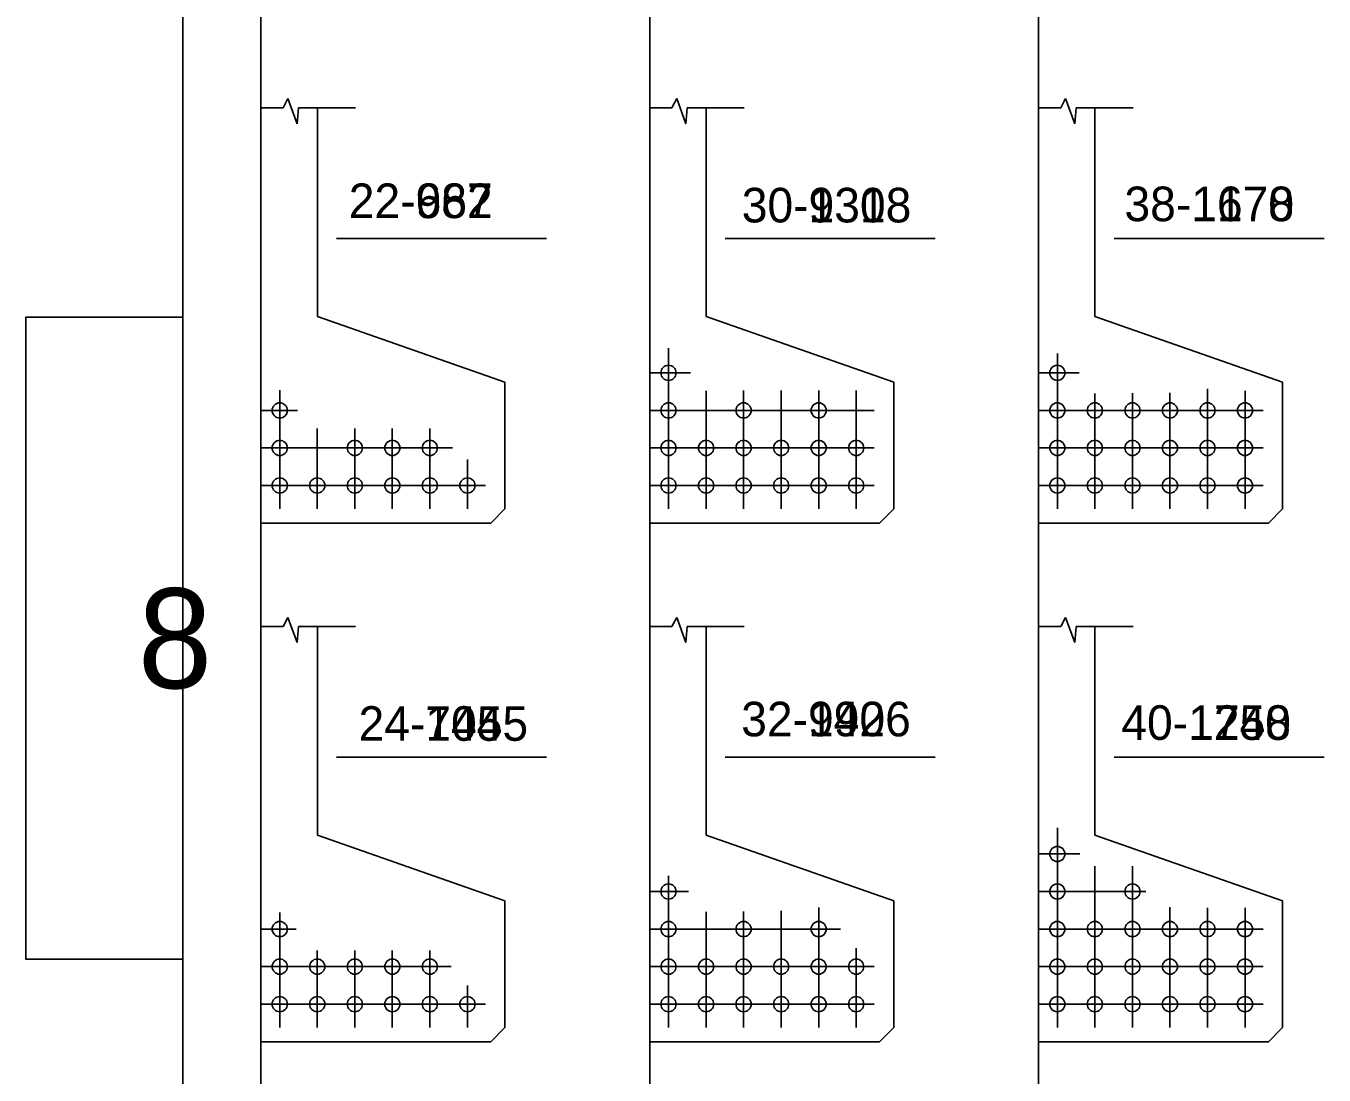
# Model space of a CAD drawing. Extents: x 1005.2 to 1101.8, y 1997.9 to 2073.7.
# Drawn here: x 1012.25 to 1024.77, y 2019.94 to 2030.05 of the extents above; entities that cross this region are included whole.
import ezdxf

# ---------------------------------------------------------------- set-up
doc = ezdxf.new("R2010")
doc.units = 0
for name, color, linetype in [('Level 1', 7, 'Continuous'), ('Level 8', 7, 'Continuous'), ('Level 9', 7, 'Continuous')]:
    doc.layers.add(name, color=color, linetype=linetype)

msp = doc.modelspace()

# ---------------------------------------------------------------- linework, layer by layer
at = {"layer": 'Level 1'}
msp.add_line((1013.763, 2012.562), (1013.763, 2068.561), dxfattribs=at)
msp.add_lwpolyline([(1013.763, 2027.241), (1012.249, 2027.241), (1012.249, 2021.051), (1013.763, 2021.051)], close=True, dxfattribs=at)
at = {"layer": 'Level 8'}
for p, q in [((1014.516, 2014.747), (1014.516, 2034.639)), ((1018.266, 2014.747), (1018.266, 2034.639)), ((1022.016, 2014.747), (1022.016, 2034.639)), ((1014.729, 2029.258), (1014.776, 2029.347)), ((1014.776, 2029.347), (1014.865, 2029.104)), ((1018.479, 2029.258), (1018.526, 2029.347)), ((1018.526, 2029.347), (1018.615, 2029.104)), ((1022.229, 2029.258), (1022.276, 2029.347)), ((1022.276, 2029.347), (1022.365, 2029.104)), ((1014.516, 2029.258), (1014.729, 2029.258)), ((1014.865, 2029.104), (1014.878, 2029.258)), ((1014.878, 2029.258), (1015.427, 2029.258)), ((1015.06, 2027.248), (1015.06, 2029.258)), ((1018.266, 2029.258), (1018.479, 2029.258)), ((1018.615, 2029.104), (1018.628, 2029.258)), ((1018.628, 2029.258), (1019.177, 2029.258)), ((1018.81, 2027.248), (1018.81, 2029.258)), ((1022.016, 2029.258), (1022.229, 2029.258)), ((1022.365, 2029.104), (1022.378, 2029.258)), ((1022.378, 2029.258), (1022.927, 2029.258)), ((1022.56, 2027.248), (1022.56, 2029.258)), ((1015.244, 2027.998), (1017.269, 2027.998)), ((1018.994, 2027.998), (1021.019, 2027.998)), ((1022.744, 2027.998), (1024.769, 2027.998)), ((1015.06, 2027.248), (1016.869, 2026.614)), ((1018.81, 2027.248), (1020.619, 2026.614)), ((1022.56, 2027.248), (1024.369, 2026.614)), ((1018.447, 2025.392), (1018.447, 2026.941)), ((1022.197, 2025.392), (1022.197, 2026.89)), ((1018.659, 2026.704), (1018.266, 2026.704)), ((1022.408, 2026.704), (1022.016, 2026.704)), ((1016.869, 2025.392), (1016.869, 2026.614)), ((1020.619, 2025.392), (1020.619, 2026.614)), ((1024.369, 2025.392), (1024.369, 2026.614)), ((1014.697, 2025.392), (1014.697, 2026.536)), ((1018.809, 2025.392), (1018.809, 2026.53)), ((1019.171, 2025.392), (1019.171, 2026.534)), ((1019.533, 2025.392), (1019.533, 2026.534)), ((1019.895, 2025.392), (1019.895, 2026.534)), ((1020.257, 2025.392), (1020.257, 2026.534)), ((1022.559, 2025.392), (1022.559, 2026.504)), ((1022.921, 2025.392), (1022.921, 2026.508)), ((1023.283, 2025.392), (1023.283, 2026.512)), ((1023.645, 2025.392), (1023.645, 2026.55)), ((1024.007, 2025.392), (1024.007, 2026.529)), ((1014.87, 2026.342), (1014.516, 2026.342)), ((1020.431, 2026.342), (1018.266, 2026.342)), ((1024.181, 2026.342), (1022.016, 2026.342)), ((1015.059, 2025.392), (1015.059, 2026.167)), ((1015.421, 2025.392), (1015.421, 2026.167)), ((1015.783, 2025.392), (1015.783, 2026.167)), ((1016.145, 2025.392), (1016.145, 2026.167)), ((1016.364, 2025.98), (1014.516, 2025.98)), ((1020.431, 2025.98), (1018.266, 2025.98)), ((1024.181, 2025.98), (1022.016, 2025.98)), ((1016.507, 2025.392), (1016.507, 2025.87)), ((1016.681, 2025.618), (1014.516, 2025.618)), ((1020.431, 2025.618), (1018.266, 2025.618)), ((1024.181, 2025.618), (1022.016, 2025.618)), ((1016.733, 2025.256), (1016.869, 2025.392)), ((1020.483, 2025.256), (1020.619, 2025.392)), ((1024.233, 2025.256), (1024.369, 2025.392)), ((1014.516, 2025.256), (1016.733, 2025.256)), ((1018.266, 2025.256), (1020.483, 2025.256)), ((1022.016, 2025.256), (1024.233, 2025.256)), ((1014.729, 2024.258), (1014.776, 2024.347)), ((1014.776, 2024.347), (1014.865, 2024.104)), ((1018.479, 2024.258), (1018.526, 2024.347)), ((1018.526, 2024.347), (1018.615, 2024.104)), ((1022.229, 2024.258), (1022.276, 2024.347)), ((1022.276, 2024.347), (1022.365, 2024.104)), ((1014.516, 2024.258), (1014.729, 2024.258)), ((1014.865, 2024.104), (1014.878, 2024.258)), ((1014.878, 2024.258), (1015.427, 2024.258)), ((1015.06, 2022.248), (1015.06, 2024.258)), ((1018.266, 2024.258), (1018.479, 2024.258)), ((1018.615, 2024.104), (1018.628, 2024.258)), ((1018.628, 2024.258), (1019.177, 2024.258)), ((1018.81, 2022.248), (1018.81, 2024.258)), ((1022.016, 2024.258), (1022.229, 2024.258)), ((1022.365, 2024.104), (1022.378, 2024.258)), ((1022.378, 2024.258), (1022.927, 2024.258)), ((1022.56, 2022.248), (1022.56, 2024.258)), ((1015.244, 2022.998), (1017.269, 2022.998)), ((1018.994, 2022.998), (1021.019, 2022.998)), ((1022.744, 2022.998), (1024.769, 2022.998)), ((1022.197, 2020.392), (1022.197, 2022.317)), ((1015.06, 2022.248), (1016.869, 2021.614)), ((1018.81, 2022.248), (1020.619, 2021.614)), ((1022.56, 2022.248), (1024.369, 2021.614)), ((1022.413, 2022.066), (1022.016, 2022.066)), ((1022.559, 2020.392), (1022.559, 2021.947)), ((1022.921, 2020.392), (1022.921, 2021.947)), ((1018.447, 2020.392), (1018.447, 2021.856)), ((1018.639, 2021.704), (1018.266, 2021.704)), ((1023.05, 2021.704), (1022.016, 2021.704)), ((1016.869, 2020.392), (1016.869, 2021.614)), ((1020.619, 2020.392), (1020.619, 2021.614)), ((1024.369, 2020.392), (1024.369, 2021.614)), ((1014.697, 2020.392), (1014.697, 2021.503)), ((1018.809, 2020.392), (1018.809, 2021.509)), ((1019.171, 2020.392), (1019.171, 2021.513)), ((1019.533, 2020.392), (1019.533, 2021.517)), ((1019.895, 2020.392), (1019.895, 2021.55)), ((1023.283, 2020.392), (1023.283, 2021.554)), ((1023.645, 2020.392), (1023.645, 2021.547)), ((1024.007, 2020.392), (1024.007, 2021.547)), ((1014.857, 2021.342), (1014.516, 2021.342)), ((1020.107, 2021.342), (1018.266, 2021.342)), ((1024.181, 2021.342), (1022.016, 2021.342)), ((1015.059, 2020.392), (1015.059, 2021.134)), ((1015.421, 2020.392), (1015.421, 2021.134)), ((1015.783, 2020.392), (1015.783, 2021.134)), ((1016.145, 2020.392), (1016.145, 2021.134)), ((1020.257, 2020.392), (1020.257, 2021.159)), ((1016.351, 2020.98), (1014.516, 2020.98)), ((1020.431, 2020.98), (1018.266, 2020.98)), ((1024.181, 2020.98), (1022.016, 2020.98)), ((1016.507, 2020.392), (1016.507, 2020.798)), ((1016.681, 2020.618), (1014.516, 2020.618)), ((1020.431, 2020.618), (1018.266, 2020.618)), ((1024.181, 2020.618), (1022.016, 2020.618)), ((1016.733, 2020.256), (1016.869, 2020.392)), ((1020.483, 2020.256), (1020.619, 2020.392)), ((1024.233, 2020.256), (1024.369, 2020.392)), ((1014.516, 2020.256), (1016.733, 2020.256)), ((1018.266, 2020.256), (1020.483, 2020.256)), ((1022.016, 2020.256), (1024.233, 2020.256))]:
    msp.add_line(p, q, dxfattribs=at)
for centre in [(1018.447, 2026.704), (1022.197, 2026.704), (1014.697, 2026.342), (1018.447, 2026.342), (1019.171, 2026.342), (1022.197, 2026.342), (1022.559, 2026.342), (1022.921, 2026.342), (1023.283, 2026.342), (1023.645, 2026.342), (1024.007, 2026.342), (1014.697, 2025.98), (1015.421, 2025.98), (1015.783, 2025.98), (1016.145, 2025.98), (1018.447, 2025.98), (1018.809, 2025.98), (1019.171, 2025.98), (1019.533, 2025.98), (1019.895, 2025.98), (1020.257, 2025.98), (1022.197, 2025.98), (1022.559, 2025.98), (1022.921, 2025.98), (1023.283, 2025.98), (1023.645, 2025.98), (1024.007, 2025.98), (1014.697, 2025.618), (1015.059, 2025.618), (1015.421, 2025.618), (1015.783, 2025.618), (1016.145, 2025.618), (1016.507, 2025.618), (1018.447, 2025.618), (1018.809, 2025.618), (1019.171, 2025.618), (1019.533, 2025.618), (1019.895, 2025.618), (1020.257, 2025.618), (1022.197, 2025.618), (1022.559, 2025.618), (1022.921, 2025.618), (1023.283, 2025.618), (1023.645, 2025.618), (1024.007, 2025.618), (1022.197, 2022.066), (1018.447, 2021.704), (1022.197, 2021.704), (1014.697, 2021.342), (1018.447, 2021.342), (1019.171, 2021.342), (1019.895, 2021.342), (1022.197, 2021.342), (1022.559, 2021.342), (1022.921, 2021.342), (1023.283, 2021.342), (1023.645, 2021.342), (1024.007, 2021.342), (1014.697, 2020.98), (1015.059, 2020.98), (1015.421, 2020.98), (1015.783, 2020.98), (1016.145, 2020.98), (1018.447, 2020.98), (1018.809, 2020.98), (1019.171, 2020.98), (1019.533, 2020.98), (1019.895, 2020.98), (1020.257, 2020.98), (1022.197, 2020.98), (1022.559, 2020.98), (1022.921, 2020.98), (1023.283, 2020.98), (1023.645, 2020.98), (1024.007, 2020.98), (1014.697, 2020.618), (1015.059, 2020.618), (1015.421, 2020.618), (1015.783, 2020.618), (1016.145, 2020.618), (1016.507, 2020.618), (1018.447, 2020.618), (1018.809, 2020.618), (1019.171, 2020.618), (1019.533, 2020.618), (1019.895, 2020.618), (1020.257, 2020.618), (1022.197, 2020.618), (1022.559, 2020.618), (1022.921, 2020.618), (1023.283, 2020.618), (1023.645, 2020.618), (1024.007, 2020.618)]:
    msp.add_circle(centre, 0.073, dxfattribs=at)
at = {"layer": 'Level 9'}
for p, q in [((1014.516, 2014.747), (1014.516, 2034.639)), ((1018.266, 2014.747), (1018.266, 2034.639)), ((1022.016, 2014.747), (1022.016, 2034.639)), ((1014.729, 2029.258), (1014.776, 2029.347)), ((1014.776, 2029.347), (1014.865, 2029.104)), ((1018.479, 2029.258), (1018.526, 2029.347)), ((1018.526, 2029.347), (1018.615, 2029.104)), ((1022.229, 2029.258), (1022.276, 2029.347)), ((1022.276, 2029.347), (1022.365, 2029.104)), ((1014.516, 2029.258), (1014.729, 2029.258)), ((1014.865, 2029.104), (1014.878, 2029.258)), ((1014.878, 2029.258), (1015.427, 2029.258)), ((1015.06, 2027.248), (1015.06, 2029.258)), ((1018.266, 2029.258), (1018.479, 2029.258)), ((1018.615, 2029.104), (1018.628, 2029.258)), ((1018.628, 2029.258), (1019.177, 2029.258)), ((1018.81, 2027.248), (1018.81, 2029.258)), ((1022.016, 2029.258), (1022.229, 2029.258)), ((1022.365, 2029.104), (1022.378, 2029.258)), ((1022.378, 2029.258), (1022.927, 2029.258)), ((1022.56, 2027.248), (1022.56, 2029.258)), ((1015.244, 2027.998), (1017.269, 2027.998)), ((1018.994, 2027.998), (1021.019, 2027.998)), ((1022.744, 2027.998), (1024.769, 2027.998)), ((1015.06, 2027.248), (1016.869, 2026.614)), ((1018.81, 2027.248), (1020.619, 2026.614)), ((1022.56, 2027.248), (1024.369, 2026.614)), ((1022.197, 2025.392), (1022.197, 2026.89)), ((1022.408, 2026.704), (1022.016, 2026.704)), ((1016.869, 2025.392), (1016.869, 2026.614)), ((1020.619, 2025.392), (1020.619, 2026.614)), ((1024.369, 2025.392), (1024.369, 2026.614)), ((1014.697, 2025.392), (1014.697, 2026.536)), ((1018.447, 2025.392), (1018.447, 2026.53)), ((1018.809, 2025.392), (1018.809, 2026.53)), ((1019.171, 2025.392), (1019.171, 2026.534)), ((1019.533, 2025.392), (1019.533, 2026.534)), ((1019.895, 2025.392), (1019.895, 2026.534)), ((1020.257, 2025.392), (1020.257, 2026.534)), ((1022.559, 2025.392), (1022.559, 2026.504)), ((1022.921, 2025.392), (1022.921, 2026.508)), ((1023.283, 2025.392), (1023.283, 2026.512)), ((1023.645, 2025.392), (1023.645, 2026.55)), ((1024.007, 2025.392), (1024.007, 2026.529)), ((1014.87, 2026.342), (1014.516, 2026.342)), ((1020.431, 2026.342), (1018.266, 2026.342)), ((1024.181, 2026.342), (1022.016, 2026.342)), ((1015.059, 2025.392), (1015.059, 2026.167)), ((1015.421, 2025.392), (1015.421, 2026.167)), ((1015.783, 2025.392), (1015.783, 2026.167)), ((1016.145, 2025.392), (1016.145, 2026.167)), ((1016.364, 2025.98), (1014.516, 2025.98)), ((1020.431, 2025.98), (1018.266, 2025.98)), ((1024.181, 2025.98), (1022.016, 2025.98)), ((1016.507, 2025.392), (1016.507, 2025.87)), ((1016.681, 2025.618), (1014.516, 2025.618)), ((1020.431, 2025.618), (1018.266, 2025.618)), ((1024.181, 2025.618), (1022.016, 2025.618)), ((1016.733, 2025.256), (1016.869, 2025.392)), ((1020.483, 2025.256), (1020.619, 2025.392)), ((1024.233, 2025.256), (1024.369, 2025.392)), ((1014.516, 2025.256), (1016.733, 2025.256)), ((1018.266, 2025.256), (1020.483, 2025.256)), ((1022.016, 2025.256), (1024.233, 2025.256)), ((1014.729, 2024.258), (1014.776, 2024.347)), ((1014.776, 2024.347), (1014.865, 2024.104)), ((1018.479, 2024.258), (1018.526, 2024.347)), ((1018.526, 2024.347), (1018.615, 2024.104)), ((1022.229, 2024.258), (1022.276, 2024.347)), ((1022.276, 2024.347), (1022.365, 2024.104)), ((1014.516, 2024.258), (1014.729, 2024.258)), ((1014.865, 2024.104), (1014.878, 2024.258)), ((1014.878, 2024.258), (1015.427, 2024.258)), ((1015.06, 2022.248), (1015.06, 2024.258)), ((1018.266, 2024.258), (1018.479, 2024.258)), ((1018.615, 2024.104), (1018.628, 2024.258)), ((1018.628, 2024.258), (1019.177, 2024.258)), ((1018.81, 2022.248), (1018.81, 2024.258)), ((1022.016, 2024.258), (1022.229, 2024.258)), ((1022.365, 2024.104), (1022.378, 2024.258)), ((1022.378, 2024.258), (1022.927, 2024.258)), ((1022.56, 2022.248), (1022.56, 2024.258)), ((1015.244, 2022.998), (1017.269, 2022.998)), ((1018.994, 2022.998), (1021.019, 2022.998)), ((1022.744, 2022.998), (1024.769, 2022.998)), ((1015.06, 2022.248), (1016.869, 2021.614)), ((1018.81, 2022.248), (1020.619, 2021.614)), ((1022.56, 2022.248), (1024.369, 2021.614)), ((1022.197, 2020.392), (1022.197, 2021.947)), ((1022.559, 2020.392), (1022.559, 2021.947)), ((1022.921, 2020.392), (1022.921, 2021.947)), ((1018.447, 2020.392), (1018.447, 2021.856)), ((1018.639, 2021.704), (1018.266, 2021.704)), ((1023.05, 2021.704), (1022.016, 2021.704)), ((1016.869, 2020.392), (1016.869, 2021.614)), ((1020.619, 2020.392), (1020.619, 2021.614)), ((1024.369, 2020.392), (1024.369, 2021.614)), ((1014.697, 2020.392), (1014.697, 2021.503)), ((1018.809, 2020.392), (1018.809, 2021.509)), ((1019.171, 2020.392), (1019.171, 2021.513)), ((1019.533, 2020.392), (1019.533, 2021.517)), ((1019.895, 2020.392), (1019.895, 2021.55)), ((1023.283, 2020.392), (1023.283, 2021.554)), ((1023.645, 2020.392), (1023.645, 2021.547)), ((1024.007, 2020.392), (1024.007, 2021.547)), ((1014.857, 2021.342), (1014.516, 2021.342)), ((1020.107, 2021.342), (1018.266, 2021.342)), ((1024.181, 2021.342), (1022.016, 2021.342)), ((1015.059, 2020.392), (1015.059, 2021.134)), ((1015.421, 2020.392), (1015.421, 2021.134)), ((1015.783, 2020.392), (1015.783, 2021.134)), ((1016.145, 2020.392), (1016.145, 2021.134)), ((1020.257, 2020.392), (1020.257, 2021.159)), ((1016.351, 2020.98), (1014.516, 2020.98)), ((1020.431, 2020.98), (1018.266, 2020.98)), ((1024.181, 2020.98), (1022.016, 2020.98)), ((1016.507, 2020.392), (1016.507, 2020.798)), ((1016.681, 2020.618), (1014.516, 2020.618)), ((1020.431, 2020.618), (1018.266, 2020.618)), ((1024.181, 2020.618), (1022.016, 2020.618)), ((1016.733, 2020.256), (1016.869, 2020.392)), ((1020.483, 2020.256), (1020.619, 2020.392)), ((1024.233, 2020.256), (1024.369, 2020.392)), ((1014.516, 2020.256), (1016.733, 2020.256)), ((1018.266, 2020.256), (1020.483, 2020.256)), ((1022.016, 2020.256), (1024.233, 2020.256))]:
    msp.add_line(p, q, dxfattribs=at)
for centre in [(1022.197, 2026.704), (1014.697, 2026.342), (1018.447, 2026.342), (1019.171, 2026.342), (1019.895, 2026.342), (1022.197, 2026.342), (1022.559, 2026.342), (1022.921, 2026.342), (1023.283, 2026.342), (1023.645, 2026.342), (1024.007, 2026.342), (1014.697, 2025.98), (1015.421, 2025.98), (1015.783, 2025.98), (1016.145, 2025.98), (1018.447, 2025.98), (1018.809, 2025.98), (1019.171, 2025.98), (1019.533, 2025.98), (1019.895, 2025.98), (1020.257, 2025.98), (1022.197, 2025.98), (1022.559, 2025.98), (1022.921, 2025.98), (1023.283, 2025.98), (1023.645, 2025.98), (1024.007, 2025.98), (1014.697, 2025.618), (1015.059, 2025.618), (1015.421, 2025.618), (1015.783, 2025.618), (1016.145, 2025.618), (1016.507, 2025.618), (1018.447, 2025.618), (1018.809, 2025.618), (1019.171, 2025.618), (1019.533, 2025.618), (1019.895, 2025.618), (1020.257, 2025.618), (1022.197, 2025.618), (1022.559, 2025.618), (1022.921, 2025.618), (1023.283, 2025.618), (1023.645, 2025.618), (1024.007, 2025.618), (1018.447, 2021.704), (1022.197, 2021.704), (1022.921, 2021.704), (1014.697, 2021.342), (1018.447, 2021.342), (1019.171, 2021.342), (1019.895, 2021.342), (1022.197, 2021.342), (1022.559, 2021.342), (1022.921, 2021.342), (1023.283, 2021.342), (1023.645, 2021.342), (1024.007, 2021.342), (1014.697, 2020.98), (1015.059, 2020.98), (1015.421, 2020.98), (1015.783, 2020.98), (1016.145, 2020.98), (1018.447, 2020.98), (1018.809, 2020.98), (1019.171, 2020.98), (1019.533, 2020.98), (1019.895, 2020.98), (1020.257, 2020.98), (1022.197, 2020.98), (1022.559, 2020.98), (1022.921, 2020.98), (1023.283, 2020.98), (1023.645, 2020.98), (1024.007, 2020.98), (1014.697, 2020.618), (1015.059, 2020.618), (1015.421, 2020.618), (1015.783, 2020.618), (1016.145, 2020.618), (1016.507, 2020.618), (1018.447, 2020.618), (1018.809, 2020.618), (1019.171, 2020.618), (1019.533, 2020.618), (1019.895, 2020.618), (1020.257, 2020.618), (1022.197, 2020.618), (1022.559, 2020.618), (1022.921, 2020.618), (1023.283, 2020.618), (1023.645, 2020.618), (1024.007, 2020.618)]:
    msp.add_circle(centre, 0.073, dxfattribs=at)

# ---------------------------------------------------------------- texts
at = {"layer": 'Level 1'}
msp.add_text('8', height=0.963, dxfattribs=at).set_placement((1013.329, 2023.664))
at = {"layer": 'Level 8'}
for s, p in [('22-682', (1015.363, 2028.196)), ('30-930', (1019.153, 2028.154)), ('38-1178', (1022.844, 2028.166)), ('24-744', (1015.457, 2023.157)), ('32-992', (1019.148, 2023.2)), ('40-1240', (1022.814, 2023.166))]:
    msp.add_text(s, height=0.3333, dxfattribs=at).set_placement(p)
at = {"layer": 'Level 9'}
for s, p in [('22-967', (1015.363, 2028.196)), ('30-1318', (1019.153, 2028.154)), ('38-1670', (1022.844, 2028.166)), ('24-1055', (1015.457, 2023.157)), ('32-1406', (1019.148, 2023.2)), ('40-1758', (1022.814, 2023.166))]:
    msp.add_text(s, height=0.3333, dxfattribs=at).set_placement(p)

doc.saveas('drawing.dxf')
